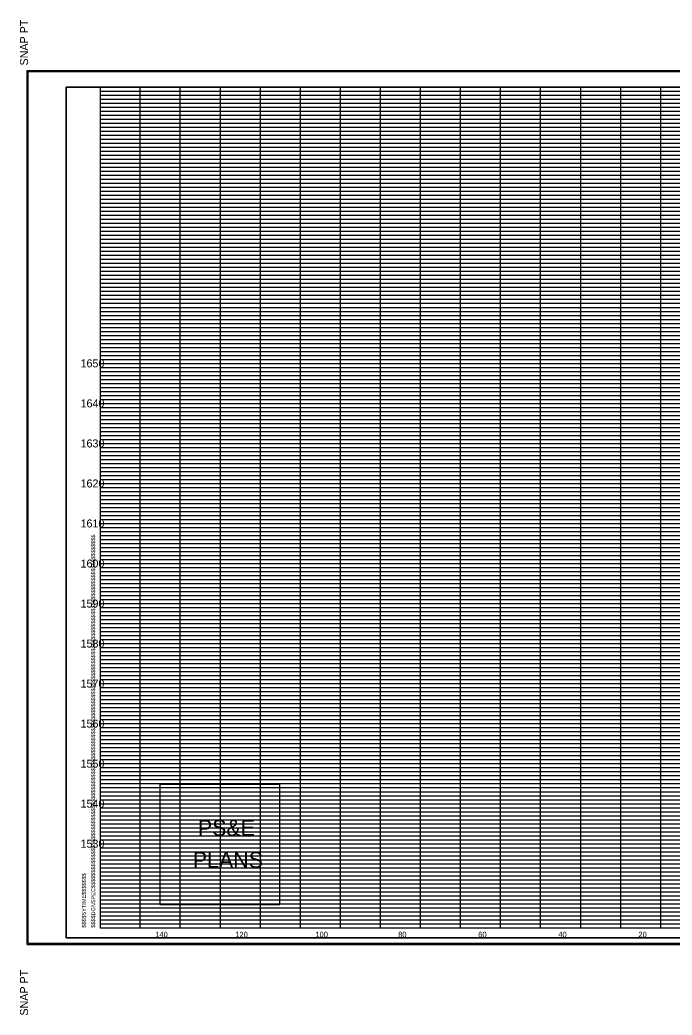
# Model space of a CAD drawing. Extents: x 980 to 1380, y 1248 to 3387.
# Drawn here: x 979.9 to 1142.8, y 3138.2 to 3386.8 of the extents above; entities that cross this region are included whole.
import ezdxf

# ---------------------------------------------------------------- set-up
doc = ezdxf.new("R2010")
doc.units = 0
for name, color, linetype in [('DESIGN - SHEET - Corner Text', 7, 'Continuous'), ('DESIGN - SHEET - Light Grid', 7, 'Continuous'), ('DESIGN - SHEET - Linework', 7, 'Continuous'), ('DESIGN - SHEET - Plot Shape', 7, 'Continuous'), ('DESIGN - TYPICAL - Text', 7, 'Continuous')]:
    doc.layers.add(name, color=color, linetype=linetype)

# ---------------------------------------------------------------- blocks, each defined once
blk = doc.blocks.new('XSTSHT')
at = {"layer": 'DESIGN - SHEET - Light Grid'}
for p, q in [((0, 20.9), (8, 20.9)), ((8, 20.9), (16, 20.9)), ((0, 20.8), (8, 20.8)), ((0, 20.7), (8, 20.7)), ((8, 20.8), (16, 20.8)), ((8, 20.7), (16, 20.7)), ((0, 20.6), (8, 20.6)), ((0, 20.5), (8, 20.5)), ((0, 20.4), (8, 20.4)), ((8, 20.6), (16, 20.6)), ((8, 20.5), (16, 20.5)), ((8, 20.4), (16, 20.4)), ((0, 20.3), (8, 20.3)), ((0, 20.2), (8, 20.2)), ((8, 20.3), (16, 20.3)), ((8, 20.2), (16, 20.2)), ((0, 20.1), (8, 20.1)), ((0, 19.9), (8, 19.9)), ((8, 20.1), (16, 20.1)), ((8, 19.9), (16, 19.9)), ((0, 19.8), (8, 19.8)), ((0, 19.7), (8, 19.7)), ((8, 19.8), (16, 19.8)), ((8, 19.7), (16, 19.7)), ((0, 19.6), (8, 19.6)), ((0, 19.5), (8, 19.5)), ((0, 19.4), (8, 19.4)), ((8, 19.6), (16, 19.6)), ((8, 19.5), (16, 19.5)), ((8, 19.4), (16, 19.4)), ((0, 19.3), (8, 19.3)), ((0, 19.2), (8, 19.2)), ((8, 19.3), (16, 19.3)), ((8, 19.2), (16, 19.2)), ((0, 19.1), (8, 19.1)), ((0, 18.9), (8, 18.9)), ((8, 19.1), (16, 19.1)), ((8, 18.9), (16, 18.9)), ((0, 18.8), (8, 18.8)), ((0, 18.7), (8, 18.7)), ((8, 18.8), (16, 18.8)), ((8, 18.7), (16, 18.7)), ((0, 18.6), (8, 18.6)), ((0, 18.5), (8, 18.5)), ((0, 18.4), (8, 18.4)), ((8, 18.6), (16, 18.6)), ((8, 18.5), (16, 18.5)), ((8, 18.4), (16, 18.4)), ((0, 18.3), (8, 18.3)), ((0, 18.2), (8, 18.2)), ((8, 18.3), (16, 18.3)), ((8, 18.2), (16, 18.2)), ((0, 18.1), (8, 18.1)), ((8, 18.1), (16, 18.1)), ((0, 17.9), (8, 17.9)), ((0, 17.8), (8, 17.8)), ((0, 17.7), (8, 17.7)), ((8, 17.9), (16, 17.9)), ((8, 17.8), (16, 17.8)), ((8, 17.7), (16, 17.7)), ((0, 17.6), (8, 17.6)), ((0, 17.5), (8, 17.5)), ((8, 17.6), (16, 17.6)), ((8, 17.5), (16, 17.5)), ((0, 17.4), (8, 17.4)), ((0, 17.3), (8, 17.3)), ((0, 17.2), (8, 17.2)), ((8, 17.4), (16, 17.4)), ((8, 17.3), (16, 17.3)), ((8, 17.2), (16, 17.2)), ((0, 17.1), (8, 17.1)), ((8, 17.1), (16, 17.1)), ((0, 16.9), (8, 16.9)), ((0, 16.8), (8, 16.8)), ((0, 16.7), (8, 16.7)), ((8, 16.9), (16, 16.9)), ((8, 16.8), (16, 16.8)), ((8, 16.7), (16, 16.7)), ((0, 16.6), (8, 16.6)), ((0, 16.5), (8, 16.5)), ((8, 16.6), (16, 16.6)), ((8, 16.5), (16, 16.5)), ((0, 16.4), (8, 16.4)), ((0, 16.3), (8, 16.3)), ((0, 16.2), (8, 16.2)), ((8, 16.4), (16, 16.4)), ((8, 16.3), (16, 16.3)), ((8, 16.2), (16, 16.2)), ((0, 16.1), (8, 16.1)), ((8, 16.1), (16, 16.1)), ((0, 15.9), (8, 15.9)), ((0, 15.8), (8, 15.8)), ((0, 15.7), (8, 15.7)), ((8, 15.9), (16, 15.9)), ((8, 15.8), (16, 15.8)), ((8, 15.7), (16, 15.7)), ((0, 15.6), (8, 15.6)), ((0, 15.5), (8, 15.5)), ((8, 15.6), (16, 15.6)), ((8, 15.5), (16, 15.5)), ((0, 15.4), (8, 15.4)), ((0, 15.3), (8, 15.3)), ((0, 15.2), (8, 15.2)), ((8, 15.4), (16, 15.4)), ((8, 15.3), (16, 15.3)), ((8, 15.2), (16, 15.2)), ((0, 15.1), (8, 15.1)), ((8, 15.1), (16, 15.1)), ((0, 14.9), (8, 14.9)), ((0, 14.8), (8, 14.8)), ((0, 14.7), (8, 14.7)), ((8, 14.9), (16, 14.9)), ((8, 14.8), (16, 14.8)), ((8, 14.7), (16, 14.7)), ((0, 14.6), (8, 14.6)), ((0, 14.5), (8, 14.5)), ((8, 14.6), (16, 14.6)), ((8, 14.5), (16, 14.5)), ((0, 14.4), (8, 14.4)), ((0, 14.3), (8, 14.3)), ((0, 14.2), (8, 14.2)), ((8, 14.4), (16, 14.4)), ((8, 14.3), (16, 14.3)), ((8, 14.2), (16, 14.2)), ((0, 14.1), (8, 14.1)), ((8, 14.1), (16, 14.1)), ((0, 13.9), (8, 13.9)), ((0, 13.8), (8, 13.8)), ((0, 13.7), (8, 13.7)), ((8, 13.9), (16, 13.9)), ((8, 13.8), (16, 13.8)), ((8, 13.7), (16, 13.7)), ((0, 13.6), (8, 13.6)), ((0, 13.5), (8, 13.5)), ((8, 13.6), (16, 13.6)), ((8, 13.5), (16, 13.5)), ((0, 13.4), (8, 13.4)), ((0, 13.3), (8, 13.3)), ((0, 13.2), (8, 13.2)), ((8, 13.4), (16, 13.4)), ((8, 13.3), (16, 13.3)), ((8, 13.2), (16, 13.2)), ((0, 13.1), (8, 13.1)), ((8, 13.1), (16, 13.1)), ((0, 12.9), (8, 12.9)), ((0, 12.8), (8, 12.8)), ((0, 12.7), (8, 12.7)), ((8, 12.9), (16, 12.9)), ((8, 12.8), (16, 12.8)), ((8, 12.7), (16, 12.7)), ((0, 12.6), (8, 12.6)), ((0, 12.5), (8, 12.5)), ((8, 12.6), (16, 12.6)), ((8, 12.5), (16, 12.5)), ((0, 12.4), (8, 12.4)), ((0, 12.3), (8, 12.3)), ((0, 12.2), (8, 12.2)), ((8, 12.4), (16, 12.4)), ((8, 12.3), (16, 12.3)), ((8, 12.2), (16, 12.2)), ((0, 12.1), (8, 12.1)), ((8, 12.1), (16, 12.1)), ((0, 11.9), (8, 11.9)), ((0, 11.8), (8, 11.8)), ((0, 11.7), (8, 11.7)), ((8, 11.9), (16, 11.9)), ((8, 11.8), (16, 11.8)), ((8, 11.7), (16, 11.7)), ((0, 11.6), (8, 11.6)), ((0, 11.5), (8, 11.5)), ((8, 11.6), (16, 11.6)), ((8, 11.5), (16, 11.5)), ((0, 11.4), (8, 11.4)), ((0, 11.3), (8, 11.3)), ((0, 11.2), (8, 11.2)), ((8, 11.4), (16, 11.4)), ((8, 11.3), (16, 11.3)), ((8, 11.2), (16, 11.2)), ((0, 11.1), (8, 11.1)), ((8, 11.1), (16, 11.1)), ((0, 10.9), (8, 10.9)), ((0, 10.8), (8, 10.8)), ((0, 10.7), (8, 10.7)), ((8, 10.9), (16, 10.9)), ((8, 10.8), (16, 10.8)), ((8, 10.7), (16, 10.7)), ((0, 10.6), (8, 10.6)), ((0, 10.5), (8, 10.5)), ((8, 10.6), (16, 10.6)), ((8, 10.5), (16, 10.5)), ((0, 10.4), (8, 10.4)), ((0, 10.3), (8, 10.3)), ((0, 10.2), (8, 10.2)), ((8, 10.4), (16, 10.4)), ((8, 10.3), (16, 10.3)), ((8, 10.2), (16, 10.2)), ((0, 10.1), (8, 10.1)), ((8, 10.1), (16, 10.1)), ((0, 9.9), (8, 9.9)), ((0, 9.8), (8, 9.8)), ((0, 9.7), (8, 9.7)), ((8, 9.9), (16, 9.9)), ((8, 9.8), (16, 9.8)), ((8, 9.7), (16, 9.7)), ((0, 9.6), (8, 9.6)), ((0, 9.5), (8, 9.5)), ((8, 9.6), (16, 9.6)), ((8, 9.5), (16, 9.5)), ((0, 9.4), (8, 9.4)), ((0, 9.3), (8, 9.3)), ((0, 9.2), (8, 9.2)), ((8, 9.4), (16, 9.4)), ((8, 9.3), (16, 9.3)), ((8, 9.2), (16, 9.2)), ((0, 9.1), (8, 9.1)), ((8, 9.1), (16, 9.1)), ((0, 8.9), (8, 8.9)), ((0, 8.8), (8, 8.8)), ((8, 8.9), (16, 8.9)), ((8, 8.8), (16, 8.8)), ((0, 8.7), (8, 8.7)), ((0, 8.6), (8, 8.6)), ((0, 8.5), (8, 8.5)), ((8, 8.7), (16, 8.7)), ((8, 8.6), (16, 8.6)), ((8, 8.5), (16, 8.5)), ((0, 8.4), (8, 8.4)), ((0, 8.3), (8, 8.3)), ((8, 8.4), (16, 8.4)), ((8, 8.3), (16, 8.3)), ((0, 8.2), (8, 8.2)), ((0, 8.1), (8, 8.1)), ((8, 8.2), (16, 8.2)), ((8, 8.1), (16, 8.1)), ((0, 7.9), (8, 7.9)), ((0, 7.8), (8, 7.8)), ((8, 7.9), (16, 7.9)), ((8, 7.8), (16, 7.8)), ((0, 7.7), (8, 7.7)), ((0, 7.6), (8, 7.6)), ((0, 7.5), (8, 7.5)), ((8, 7.7), (16, 7.7)), ((8, 7.6), (16, 7.6)), ((8, 7.5), (16, 7.5)), ((0, 7.4), (8, 7.4)), ((0, 7.3), (8, 7.3)), ((8, 7.4), (16, 7.4)), ((8, 7.3), (16, 7.3)), ((0, 7.2), (8, 7.2)), ((0, 7.1), (8, 7.1)), ((8, 7.2), (16, 7.2)), ((8, 7.1), (16, 7.1)), ((0, 6.9), (8, 6.9)), ((0, 6.8), (8, 6.8)), ((8, 6.9), (16, 6.9)), ((8, 6.8), (16, 6.8)), ((0, 6.7), (8, 6.7)), ((0, 6.6), (8, 6.6)), ((0, 6.5), (8, 6.5)), ((8, 6.7), (16, 6.7)), ((8, 6.6), (16, 6.6)), ((8, 6.5), (16, 6.5)), ((0, 6.4), (8, 6.4)), ((0, 6.3), (8, 6.3)), ((8, 6.4), (16, 6.4)), ((8, 6.3), (16, 6.3)), ((0, 6.2), (8, 6.2)), ((0, 6.1), (8, 6.1)), ((8, 6.2), (16, 6.2)), ((8, 6.1), (16, 6.1)), ((0, 5.9), (8, 5.9)), ((0, 5.8), (8, 5.8)), ((8, 5.9), (16, 5.9)), ((8, 5.8), (16, 5.8)), ((0, 5.7), (8, 5.7)), ((0, 5.6), (8, 5.6)), ((0, 5.5), (8, 5.5)), ((8, 5.7), (16, 5.7)), ((8, 5.6), (16, 5.6)), ((8, 5.5), (16, 5.5)), ((0, 5.4), (8, 5.4)), ((0, 5.3), (8, 5.3)), ((8, 5.4), (16, 5.4)), ((8, 5.3), (16, 5.3)), ((0, 5.2), (8, 5.2)), ((0, 5.1), (8, 5.1)), ((8, 5.2), (16, 5.2)), ((8, 5.1), (16, 5.1)), ((0, 4.9), (8, 4.9)), ((0, 4.8), (8, 4.8)), ((8, 4.9), (16, 4.9)), ((8, 4.8), (16, 4.8)), ((0, 4.7), (8, 4.7)), ((0, 4.6), (8, 4.6)), ((0, 4.5), (8, 4.5)), ((8, 4.7), (16, 4.7)), ((8, 4.6), (16, 4.6)), ((8, 4.5), (16, 4.5)), ((0, 4.4), (8, 4.4)), ((0, 4.3), (8, 4.3)), ((8, 4.4), (16, 4.4)), ((8, 4.3), (16, 4.3)), ((0, 4.2), (8, 4.2)), ((0, 4.1), (8, 4.1)), ((8, 4.2), (16, 4.2)), ((8, 4.1), (16, 4.1)), ((0, 3.9), (8, 3.9)), ((0, 3.8), (8, 3.8)), ((8, 3.9), (16, 3.9)), ((8, 3.8), (16, 3.8)), ((0, 3.7), (8, 3.7)), ((0, 3.6), (8, 3.6)), ((0, 3.5), (8, 3.5)), ((8, 3.7), (16, 3.7)), ((8, 3.6), (16, 3.6)), ((8, 3.5), (16, 3.5)), ((0, 3.4), (8, 3.4)), ((0, 3.3), (8, 3.3)), ((8, 3.4), (16, 3.4)), ((8, 3.3), (16, 3.3)), ((0, 3.2), (8, 3.2)), ((0, 3.1), (8, 3.1)), ((8, 3.2), (16, 3.2)), ((8, 3.1), (16, 3.1)), ((0, 2.9), (8, 2.9)), ((0, 2.8), (8, 2.8)), ((8, 2.9), (16, 2.9)), ((8, 2.8), (16, 2.8)), ((0, 2.7), (8, 2.7)), ((0, 2.6), (8, 2.6)), ((0, 2.5), (8, 2.5)), ((8, 2.7), (16, 2.7)), ((8, 2.6), (16, 2.6)), ((8, 2.5), (16, 2.5)), ((0, 2.4), (8, 2.4)), ((0, 2.3), (8, 2.3)), ((8, 2.4), (16, 2.4)), ((8, 2.3), (16, 2.3)), ((0, 2.2), (8, 2.2)), ((0, 2.1), (8, 2.1)), ((8, 2.2), (16, 2.2)), ((8, 2.1), (16, 2.1)), ((0, 1.9), (8, 1.9)), ((0, 1.8), (8, 1.8)), ((8, 1.9), (16, 1.9)), ((8, 1.8), (16, 1.8)), ((0, 1.7), (8, 1.7)), ((0, 1.6), (8, 1.6)), ((0, 1.5), (8, 1.5)), ((8, 1.7), (16, 1.7)), ((8, 1.6), (16, 1.6)), ((8, 1.5), (16, 1.5)), ((0, 1.4), (8, 1.4)), ((0, 1.3), (8, 1.3)), ((8, 1.4), (16, 1.4)), ((8, 1.3), (16, 1.3)), ((0, 1.2), (8, 1.2)), ((0, 1.1), (8, 1.1)), ((8, 1.2), (16, 1.2)), ((8, 1.1), (16, 1.1)), ((0, 0.9), (8, 0.9)), ((0, 0.8), (8, 0.8)), ((8, 0.9), (16, 0.9)), ((8, 0.8), (16, 0.8)), ((0, 0.7), (8, 0.7)), ((0, 0.6), (8, 0.6)), ((0, 0.5), (8, 0.5)), ((8, 0.7), (16, 0.7)), ((8, 0.6), (16, 0.6)), ((8, 0.5), (16, 0.5)), ((0, 0.4), (8, 0.4)), ((0, 0.3), (8, 0.3)), ((8, 0.4), (16, 0.4)), ((8, 0.3), (16, 0.3)), ((0, 0.2), (8, 0.2)), ((0, 0.1), (8, 0.1)), ((8, 0.2), (16, 0.2)), ((8, 0.1), (16, 0.1))]:
    blk.add_line(p, q, dxfattribs=at)
at = {"layer": 'DESIGN - SHEET - Linework'}
for p, q in [((-1.823, -0.414), (-1.823, 21.414)), ((-1.823, 21.414), (32.217, 21.414)), ((1, 0), (1, 21)), ((2, 0), (2, 21)), ((3, 0), (3, 21)), ((4, 0), (4, 21)), ((5, 0), (5, 21)), ((6, 0), (6, 21)), ((7, 0), (7, 21)), ((8, 0), (8, 21)), ((9, 0), (9, 21)), ((10, 0), (10, 21)), ((11, 0), (11, 21)), ((12, 0), (12, 21)), ((13, 0), (13, 21)), ((14, 0), (14, 21)), ((0, 20), (28, 20)), ((0, 19), (32, 19)), ((0, 18), (32, 18)), ((0, 17), (32, 17)), ((0, 16), (32, 16)), ((0, 15), (32, 15)), ((0, 14), (32, 14)), ((0, 13), (32, 13)), ((0, 12), (32, 12)), ((0, 11), (32, 11)), ((0, 10), (32, 10)), ((0, 9), (32, 9)), ((0, 8), (32, 8)), ((0, 7), (32, 7)), ((0, 6), (32, 6)), ((0, 5), (32, 5)), ((0, 4), (32, 4)), ((0, 3), (32, 3)), ((0, 2), (32, 2)), ((0, 1), (32, 1)), ((-1.823, -0.414), (32.217, -0.414))]:
    blk.add_line(p, q, dxfattribs=at)
blk.add_lwpolyline([(0, 21), (0, 0), (32, 0), (32, 21), (0, 21)], dxfattribs=at)
at = {"layer": 'DESIGN - SHEET - Plot Shape'}
for points in [[(-1.803, 21.394), (32.197, 21.394), (32.197, -0.394), (-1.803, -0.394)], [(-0.85, 21), (32, 21), (32, -0.25), (-0.85, -0.25)]]:
    blk.add_lwpolyline(points, close=True, dxfattribs=at)
at = {"layer": 'DESIGN - SHEET - Corner Text'}
for s, height, p in [('  SNAP PT', 0.2, (-1.803, 21.394)), ('$$$$DGNSPEC$$$$$$$$$$$$$$$$$$$$$$$$$$$$$$$$$$$$$$$$$$$$$$$$$$$$$$$$$$$$$$$$$$$$$$$$$$$$$$$$$$$$$$$$$$$$$$$$$$$$$$$$$$$$$$$$$$$', 0.100002, (-0.126, 0)), ('$$$$SYTIME$$$$$$$', 0.1, (-0.358, 0)), ('SNAP PT  ', 0.2, (-1.803, -2.194))]:
    blk.add_text(s, height=height, rotation=90, dxfattribs=at).set_placement(p)

msp = doc.modelspace()

# ---------------------------------------------------------------- linework, layer by layer
at = {"layer": 'DESIGN - SHEET - Corner Text'}
msp.add_lwpolyline([(1014.87, 3195.8), (1014.87, 3165.8), (1044.87, 3165.8), (1044.87, 3195.8)], close=True, dxfattribs=at)
at = {"layer": 'DESIGN - SHEET - Plot Shape'}
msp.add_lwpolyline([(991.5, 3157.5), (1320, 3157.5), (1320, 3370), (991.5, 3370)], close=True, dxfattribs=at)

# ---------------------------------------------------------------- block references
at = {"layer": 'DESIGN - TYPICAL - Text', "xscale": 10, "yscale": 10}
msp.add_blockref('XSTSHT', (1000, 3160), dxfattribs=at)

# ---------------------------------------------------------------- texts
at = {"layer": 'DESIGN - SHEET - Corner Text'}
for s, p in [('PS&E', (1024.39, 3182.97)), ('PLANS', (1023.11, 3174.97))]:
    msp.add_text(s, height=4, dxfattribs=at).set_placement(p)
at = {"layer": 'DESIGN - TYPICAL - Text'}
for s, height, p in [('     1650     ', 2, (991.37, 3300)), ('     1640     ', 2, (991.37, 3290)), ('     1630     ', 2, (991.37, 3280)), ('     1620     ', 2, (991.37, 3270)), ('     1610     ', 2, (991.37, 3260)), ('     1600     ', 2, (991.37, 3250)), ('     1590     ', 2, (991.37, 3240)), ('     1580     ', 2, (991.37, 3230)), ('     1570     ', 2, (991.37, 3220)), ('     1560     ', 2, (991.37, 3210)), ('     1550     ', 2, (991.37, 3200)), ('     1540     ', 2, (991.37, 3190)), ('     1530     ', 2, (991.37, 3180)), ('     140     ', 1.4, (1011.14, 3157.6)), ('     120     ', 1.4, (1031.14, 3157.6)), ('     100     ', 1.4, (1051.14, 3157.6)), ('     80     ', 1.4, (1071.82, 3157.6)), ('     60     ', 1.4, (1091.82, 3157.6)), ('     40     ', 1.4, (1111.82, 3157.6)), ('     20     ', 1.4, (1131.82, 3157.6))]:
    msp.add_text(s, height=height, dxfattribs=at).set_placement(p)

doc.saveas('drawing.dxf')
